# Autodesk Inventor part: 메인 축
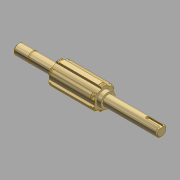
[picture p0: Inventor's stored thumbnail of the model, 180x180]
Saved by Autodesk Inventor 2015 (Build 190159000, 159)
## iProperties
Created: 2015-11
Part Number: 메인 축
Document SubType Name: 모델링
Designer: mdu
Mass: 21.4462 g
Surface Area: 72.5109 cm^2
Volume: 21.4462 cm^3
Density: 1 g/cm^3
Material: 일반
Appearance: 기본값
변환 표준: STEP AP214IS
파일 이름: C:\Users\SeoGD\Desktop\?쒗뿕\硫붿씤 異?.stp
전처리기: Build: 253, Release: 2010 SP1 - Date: Wed 07/29/2009
전송 단위: 밀리미터
불확실성: 0.01
Author: mdu
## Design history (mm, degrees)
sketch "스케치1"
  geometry: L1 (-69.5, 0)-(69.5, 0); L2 (69.5, 0)-(69.5, 5); L3 (69.5, 5)-(55.5, 5); L4 (55.5, 5)-(55.5, 4.8); L5 (55.5, 4.8)-(54.35, 4.8); L6 (54.35, 4.8)-(54.35, 5); L7 (54.35, 5)-(30.5, 5); L8 (30.5, 5)-(30.5, 9); L9 (30.5, 9)-(-13.5, 9); L10 (-13.5, 9)-(-13.5, 7); L11 (-13.5, 7)-(-17.5, 7); L12 (-17.5, 7)-(-17.5, 5); L13 (-17.5, 5)-(-69.5, 5); L14 (-69.5, 5)-(-69.5, 0); 2 further points
  constraints: 28 end point, 9 parallel, 4 collinear, 2 perpendicular, 1 coincident, 1 horizontal, 1 midpoint
  dimensions: "d2" = 1.15 distance between parallel lines of L6 L4; "d3" = 10 diameter of L3 L1; "d4" = 9.6 diameter of L5 L1; "d6" = 44 distance between parallel lines of L10 L8; "d7" = 4 distance between parallel lines of L12 L10; "d8" = 14 diameter of L11 L1; "d9" = 18 diameter of L9 L1; "d33" = 52 distance from line of L12.end L14; "d37" = 39 distance between parallel lines of L8 L2; "d38" = 14 distance between parallel lines of L2 L4
revolve "회전1" sketch "스케치1" stored, may be unused: angle "d10" = 90 deg
sketch "스케치2"
  geometry: L1 (2.5, 10.712)-(2.5, 8.646); L2 (-2.5, 10.712)-(-2.5, 8.646); A1 r 9 centre (0, 0) between (2.5, 8.646) and (-2.5, 8.646) reference; A2 r 11 centre (0, 0) between (2.5, 10.712) and (-2.5, 10.712); 1 further point
  constraints: 4 end point, 4 point on circle, 2 parallel, 1 centre point, 1 coincident, 1 vertical
  dimensions: "d11" = 22 diameter of A2; "d12" = 5 distance between parallel lines of L1 L2
extrude "돌출1" join sketch "스케치2" stored distance "d13" = 10; taper "d14" = 0 deg
chamfer "모따기1" distance "d15" = 1; stored, may be unused: second distance "d16" = 2, angle "d17" = 45 deg
node "작업 평면1"
node "작업 평면2"
sketch "스케치3"
  geometry: L1 (2.5, 10.712)-(2.5, 10.198); L2 (-2.5, 10.712)-(-2.5, 10.198); A1 r 11 centre (0, 0) between (2.5, 10.712) and (-2.5, 10.712) reference; A2 r 10.5 centre (0, 0) between (2.5, 10.198) and (-2.5, 10.198); 1 further point
  constraints: 4 end point, 2 point on circle, 1 centre point, 1 coincident, 1 parallel, 1 vertical
  dimensions: "d19" = 21 diameter of A2
extrude "돌출2" cut sketch "스케치3" distance "d20" = 1.35; taper "d21" = 0 deg
node "작업 평면3"
sketch "스케치4"
  geometry: L1 (-26, -5)-(-26, 5) reference; L2 (-26, 1.5)-(-12.5, 1.5); L3 (-12.5, -1.5)-(-26, -1.5); A1 r 1.5 centre (-12.5, 0) between (-12.5, -1.5) and (-12.5, 1.5); 2 further points
  constraints: 4 end point, 2 perpendicular, 2 point on circle, 2 point on line, 2 tangent, 1 centre point, 1 horizontal alignment, 1 midpoint
  dimensions: "d25" = 3 distance between parallel lines of L3 L2; "d26" = 15 dimension on A1 L1
extrude "돌출3" cut sketch "스케치4" distance "d27" = 1.8; taper "d28" = 0 deg
chamfer "모따기2" distance "d29" = 1; stored, may be unused: second distance "d30" = 2, angle "d31" = 45 deg
node "솔리드1"
node "솔리드 본체"
node "곡면 본체"
mirror "대칭1"
pattern_circular "원형 패턴1" dims "d23" = 360 deg
node "솔리드2"
other parameters: "d18" = -1.65
